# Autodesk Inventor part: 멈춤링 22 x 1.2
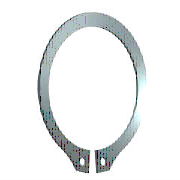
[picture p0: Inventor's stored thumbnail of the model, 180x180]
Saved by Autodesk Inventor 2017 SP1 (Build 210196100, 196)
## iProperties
IsCustomPart: 0
Created: 2021-07
Part Number: 멈춤링 22 x 1.2
Material: 강철, 연강
Description: 리테이닝 링(C형)
Document SubType Name: Modeling
Standard: KS B 1336
Designer: mdu
Standards Organization: KS
Language: ko-KR
Size Designation: 22 x 1.2
Categories: <MemberInstance><Categories><Category DisplayName="샤프트 부품" InternalName="7f7aeb1f-a693-4053-b835-cee3144e0d98" Mnemonic="SHFT"><Category DisplayName="써클립" Inter
Density: 7.86 g/cm^3
Mass: 1.8286 g
Surface Area: 5.91219 cm^2
Volume: 0.232646 cm^3
Appearance: 파란색 - 벽 페인트 - 광택
Author: mdu
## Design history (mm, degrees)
sketch "스케치1"
  geometry: L1 (-6, 0)-(6, 0) reference; L2 (0, 20.189)-(0, -80.536) reference; L3 (-48.09, 0)-(48.09, 0) reference; L4 (-0.5, -21.488)-(-0.5, -25.588); L5 (-0.5, -6.54)-(-0.5, -13.29); L6 (-2.795, 2.7)-(3.672, 2.7); L7 (0.5, -6.54)-(0.5, -13.29); L8 (0.5, -21.488)-(0.5, -25.588); C1 r 1 at (-2, -23.437); C2 r 1 at (2, -23.437); A1 r 10.5 centre (0, -11) between (0.5, -21.488) and (-0.5, -21.488); A2 r 13.025 centre (0, -10.325) between (5.149, -22.289) and (-5.149, -22.289); A3 r 14.597 centre (0, -11) between (-2.318, -25.411) and (-0.5, -25.588); A4 r 2 centre (-2, -23.437) between (-3.97, -23.781) and (-2.318, -25.411); A5 r 2 centre (-5.94, -24.126) between (-3.97, -23.781) and (-5.149, -22.289); A6 r 2 centre (5.94, -24.126) between (5.149, -22.289) and (3.97, -23.781); A7 r 2 centre (2, -23.437) between (2.318, -25.411) and (3.97, -23.781); A8 r 14.597 centre (0, -11) between (0.5, -25.588) and (2.318, -25.411)
  constraints: 16 point on circle, 12 end point, 10 centre point, 9 symmetric about line, 5 point on line, 4 tangent, 3 coincident, 2 horizontal, 1 perpendicular, 1 vertical, 5 other
  dimensions: "d0" = 21 diameter of A1 (= ND); "d1" = 4.1 distance of L4.end L4.start (= SRB2); "d6" = 0.5 distance between parallel lines of L2 L5 (= 0.25 x SD5); "d7" = 2.7 distance between parallel lines of L6 L3 (= SRB1); "d8" = 0.675 distance of A1.centre A2.centre (= 0.25 x SRB1); "d9" = 2 radius of A4 (= SD5); "d10" = 2 radius of A5 (= SD5); "d11" = 1.5 distance from line of L4 A4.centre (= 0.75 x SD5); "d12" = 2 diameter of C1 (= SD5); "d13" = 2 diameter of C2 (= SD5); "d14" = 11 distance from line of A1.centre L1 (= 0.5 x WD)
extrude "본체" new body sketch "스케치1" distance "d2" = 1.2 (= SD); taper "d3" = 0 deg
workaxis "Work Axis1"
workplane "Work Plane1"
body "Solid1"
other parameters: "WD" = 22 (= WDMIN) [user parameter; used in 1 equation term], "SD" = 1.2 [user parameter; used in 1 equation term], "SRB1" = 2.7 [user parameter; used in 2 equation terms], "ND" = 21 [user parameter; used in 1 equation term], "SRB2" = 4.1 [user parameter; used in 1 equation term], "SD5" = 2 [user parameter; used in 6 equation terms], "d15" = 0, "d16" = 0, "d17" = 0, "d41" = 0, "d42" = 0, "WDMIN" = 22 [user parameter; used in 1 equation term], "SD3" = 20.5 [user parameter], "WDMAX" = 24 [user parameter]
